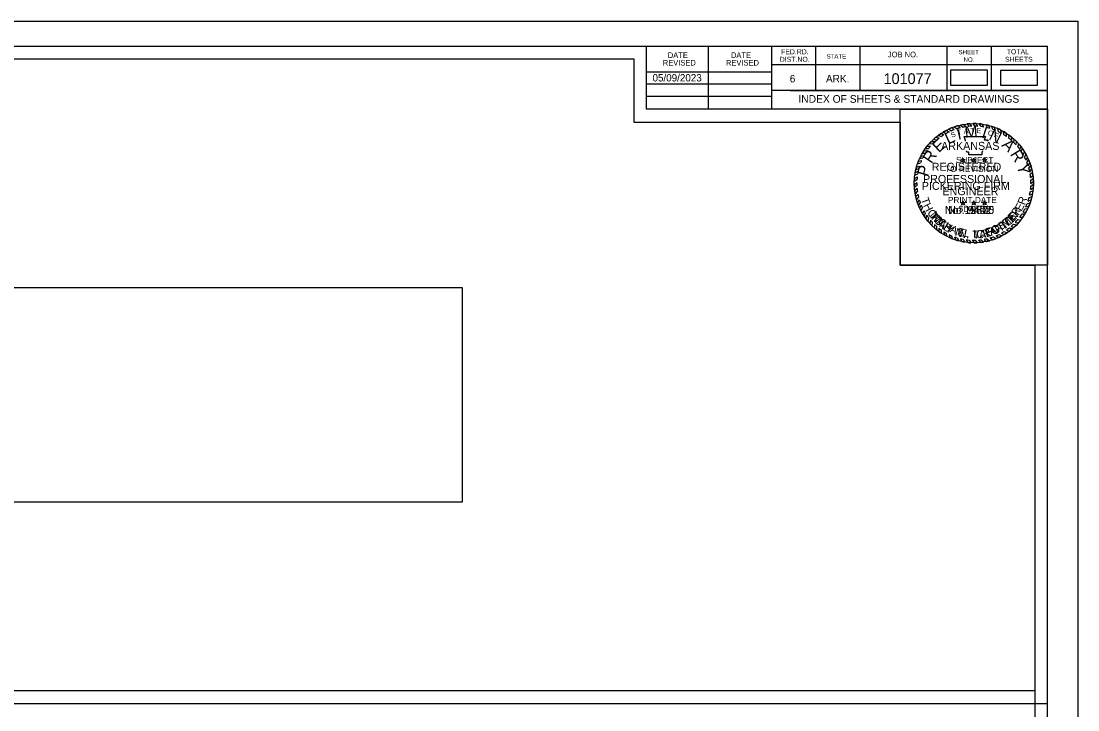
# Model space of a CAD drawing. Extents: x 1369905 to 1370238, y 380119 to 380332.
# Drawn here: x 1370072.9 to 1370238, y 380224.8 to 380332.4 of the extents above; entities that cross this region are included whole.
import ezdxf

# ---------------------------------------------------------------- set-up
doc = ezdxf.new("R2010")
doc.units = 0
for name, color, linetype in [('Default', 7, 'Continuous'), ('R_Border', 7, 'Continuous'), ('R_Border Notes', 7, 'Continuous'), ('R_Border Plan-Plan', 7, 'Continuous'), ('R_No Plot', 7, 'Continuous'), ('R_Revision Date Text', 7, 'Continuous'), ('STAMP_PE_CRAFTON', 7, 'Continuous'), ('STAMP_PE_FOSTER', 7, 'Continuous'), ('STAMP_PE_SEAL-INFO', 7, 'Continuous'), ('STAMP_PE_TAEGTMEYER', 7, 'Continuous'), ('STAMP_PE_TXT', 7, 'Continuous'), ('STAMP_PRELIMINARY', 7, 'Continuous')]:
    doc.layers.add(name, color=color, linetype=linetype)

msp = doc.modelspace()

# ---------------------------------------------------------------- linework, layer by layer
at = {"layer": 'Default'}
for points in [[(1370218.08, 380322.41), (1370223.88, 380322.41), (1370223.88, 380324.71), (1370218.08, 380324.71)], [(1370225.91, 380322.39), (1370231.71, 380322.39), (1370231.71, 380324.69), (1370225.91, 380324.69)], [(1369997.28, 380257.3), (1370141.89, 380257.3), (1370141.89, 380290.72), (1369997.28, 380290.72)]]:
    msp.add_lwpolyline(points, close=True, dxfattribs=at)
at = {"layer": 'R_Border'}
for p, q in [((1369917.07, 380328.5), (1370233.25, 380328.5)), ((1370170.61, 380318.62), (1370170.61, 380328.5)), ((1370180.29, 380318.62), (1370180.29, 380328.5)), ((1370190.15, 380328.5), (1370190.15, 380318.62)), ((1370196.99, 380328.5), (1370196.99, 380321.56)), ((1370203.93, 380328.5), (1370203.93, 380321.56)), ((1370217.51, 380328.5), (1370217.51, 380321.56)), ((1370224.45, 380328.5), (1370224.45, 380321.56)), ((1370233.25, 380123.04), (1370233.25, 380328.5)), ((1370170.61, 380324.48), (1370190.15, 380324.48)), ((1370233.25, 380325.56), (1370190.15, 380325.56)), ((1370233.25, 380325.58), (1370233.25, 380325.58)), ((1370170.61, 380322.62), (1370190.15, 380322.62)), ((1370233.25, 380321.56), (1370190.15, 380321.56)), ((1370193.11, 380321.56), (1370233.25, 380321.56)), ((1370170.61, 380320.68), (1370190.15, 380320.68)), ((1370233.25, 380318.62), (1370170.61, 380318.62))]:
    msp.add_line(p, q, dxfattribs=at)
at = {"layer": 'R_Border Plan-Plan'}
msp.add_line((1369917.07, 380225.77), (1370233.25, 380225.77), dxfattribs=at)
at = {"layer": 'R_No Plot'}
for points in [[(1369904.66, 380332.4), (1370238, 380332.4), (1370238, 380119.06), (1369904.66, 380119.06)], [(1370231.25, 380227.77), (1369919.07, 380227.77), (1369919.07, 380326.5), (1370168.61, 380326.5), (1370168.61, 380316.62), (1370186.15, 380316.62), (1370210.25, 380316.62), (1370210.25, 380294.29), (1370231.25, 380294.29)], [(1369919.07, 380326.5), (1370168.61, 380326.5), (1370168.61, 380316.62), (1370186.15, 380316.62), (1370210.25, 380316.62), (1370210.25, 380294.29), (1370231.25, 380294.29), (1370231.25, 380125.04), (1369919.07, 380125.04)], [(1370210.25, 380318.62), (1370233.25, 380318.62), (1370233.25, 380294.29), (1370210.25, 380294.29)]]:
    msp.add_lwpolyline(points, close=True, dxfattribs=at)
at = {"layer": 'STAMP_PE_SEAL-INFO'}
for p, q in [((1370218.71, 380315.88), (1370219.09, 380315.57)), ((1370219.3, 380316.06), (1370219.58, 380315.71)), ((1370219.68, 380316.16), (1370220.04, 380315.81)), ((1370220.17, 380316.25), (1370220.47, 380315.89)), ((1370220.68, 380316.33), (1370220.96, 380315.95)), ((1370221.42, 380315.97), (1370221.11, 380316.37)), ((1370221.92, 380315.98), (1370221.64, 380316.39)), ((1370222.37, 380315.96), (1370222.12, 380316.38)), ((1370222.88, 380315.91), (1370222.59, 380316.35)), ((1370223.3, 380315.84), (1370223.05, 380316.3)), ((1370223.87, 380315.72), (1370223.69, 380316.18)), ((1370224.27, 380315.62), (1370224.11, 380316.08)), ((1370224.72, 380315.47), (1370224.58, 380315.95)), ((1370215.79, 380314.24), (1370216.32, 380314.13)), ((1370216.16, 380314.56), (1370216.62, 380314.36)), ((1370216.58, 380314.83), (1370217.03, 380314.63)), ((1370216.97, 380315.07), (1370217.4, 380314.85)), ((1370217.42, 380315.32), (1370217.88, 380315.1)), ((1370217.85, 380315.54), (1370218.24, 380315.26)), ((1370218.36, 380315.75), (1370218.65, 380315.43)), ((1370220.22, 380314.36), (1370223.56, 380314.36)), ((1370220.34, 380314.05), (1370220.22, 380314.36)), ((1370223.56, 380314.36), (1370223.34, 380313.87)), ((1370225.14, 380315.31), (1370224.99, 380315.8)), ((1370225.6, 380315.1), (1370225.5, 380315.6)), ((1370226.05, 380314.87), (1370225.96, 380315.38)), ((1370226.43, 380314.65), (1370226.39, 380315.15)), ((1370226.87, 380314.36), (1370226.84, 380314.88)), ((1370227.23, 380314.09), (1370227.26, 380314.58)), ((1370227.68, 380313.72), (1370227.69, 380314.24)), ((1370214.44, 380312.86), (1370214.99, 380312.88)), ((1370214.78, 380313.27), (1370215.31, 380313.23)), ((1370215.11, 380313.61), (1370215.65, 380313.57)), ((1370215.44, 380313.94), (1370215.9, 380313.8)), ((1370220.44, 380313.75), (1370220.34, 380314.05)), ((1370220.45, 380313.64), (1370220.44, 380313.75)), ((1370223.34, 380313.87), (1370223.97, 380313.87)), ((1370223.97, 380313.87), (1370223.83, 380313.64)), ((1370227.99, 380313.43), (1370228.06, 380313.93)), ((1370228.35, 380313.06), (1370228.41, 380313.58)), ((1370228.62, 380312.74), (1370228.76, 380313.21)), ((1370228.94, 380312.32), (1370229.08, 380312.82)), ((1370213.26, 380310.93), (1370213.76, 380311.03)), ((1370213.45, 380311.32), (1370213.95, 380311.38)), ((1370213.68, 380311.74), (1370214.17, 380311.76)), ((1370213.93, 380312.14), (1370214.44, 380312.18)), ((1370214.16, 380312.49), (1370214.67, 380312.48)), ((1370220.64, 380311.93), (1370220.62, 380312.15)), ((1370220.96, 380311.93), (1370220.64, 380311.93)), ((1370220.96, 380311.5), (1370220.96, 380311.93)), ((1370222.99, 380311.5), (1370220.96, 380311.5)), ((1370223, 380311.84), (1370222.99, 380311.5)), ((1370223.08, 380312.15), (1370223, 380311.84)), ((1370229.16, 380312.01), (1370229.34, 380312.47)), ((1370229.47, 380311.51), (1370229.66, 380312)), ((1370229.67, 380311.14), (1370229.9, 380311.59)), ((1370229.9, 380310.66), (1370230.13, 380311.14)), ((1370212.67, 380309.18), (1370213.14, 380309.37)), ((1370212.77, 380309.59), (1370213.25, 380309.76)), ((1370212.93, 380310.09), (1370213.41, 380310.23)), ((1370213.08, 380310.5), (1370213.58, 380310.64)), ((1370230.04, 380310.32), (1370230.31, 380310.76)), ((1370230.24, 380309.77), (1370230.51, 380310.25)), ((1370230.35, 380309.41), (1370230.64, 380309.86)), ((1370230.48, 380308.85), (1370230.8, 380309.3)), ((1370212.85, 380307.61), (1370212.43, 380307.36)), ((1370212.89, 380308.04), (1370212.45, 380307.76)), ((1370212.94, 380308.48), (1370212.5, 380308.25)), ((1370213.03, 380308.93), (1370212.56, 380308.69)), ((1370230.55, 380308.47), (1370230.9, 380308.82)), ((1370230.61, 380307.96), (1370230.99, 380308.3)), ((1370230.65, 380307.54), (1370231.04, 380307.83)), ((1370212.83, 380307.12), (1370212.43, 380306.79)), ((1370212.84, 380306.71), (1370212.45, 380306.39)), ((1370212.87, 380306.22), (1370212.5, 380305.86)), ((1370230.61, 380306.11), (1370231.04, 380306.37)), ((1370230.65, 380306.62), (1370231.07, 380306.9)), ((1370230.66, 380307.02), (1370231.06, 380307.35)), ((1370212.92, 380305.79), (1370212.57, 380305.42)), ((1370213, 380305.33), (1370212.66, 380304.96)), ((1370213.1, 380304.91), (1370212.78, 380304.5)), ((1370213.22, 380304.46), (1370212.93, 380304.05)), ((1370230.21, 380304.28), (1370230.7, 380304.48)), ((1370230.36, 380304.77), (1370230.83, 380304.97)), ((1370230.47, 380305.22), (1370230.92, 380305.42)), ((1370230.56, 380305.72), (1370231, 380305.94)), ((1370213.36, 380304.04), (1370213.08, 380303.63)), ((1370213.53, 380303.62), (1370213.27, 380303.19)), ((1370213.7, 380303.23), (1370213.47, 380302.77)), ((1370213.93, 380302.77), (1370213.74, 380302.28)), ((1370229.7, 380303.05), (1370230.19, 380303.12)), ((1370229.86, 380303.38), (1370230.35, 380303.48)), ((1370230.08, 380303.9), (1370230.56, 380304.03)), ((1370214.17, 380302.37), (1370213.99, 380301.9)), ((1370214.37, 380302.06), (1370214.26, 380301.51)), ((1370214.65, 380301.67), (1370214.55, 380301.14)), ((1370214.96, 380301.29), (1370214.87, 380300.77)), ((1370228.61, 380301.38), (1370229.07, 380301.3)), ((1370228.92, 380301.77), (1370229.42, 380301.78)), ((1370229.26, 380302.27), (1370229.74, 380302.26)), ((1370229.43, 380302.55), (1370229.93, 380302.6)), ((1370215.26, 380300.95), (1370215.2, 380300.43)), ((1370215.58, 380300.63), (1370215.55, 380300.1)), ((1370215.93, 380300.31), (1370215.92, 380299.79)), ((1370216.29, 380300.02), (1370216.3, 380299.5)), ((1370216.62, 380299.77), (1370216.66, 380299.25)), ((1370217.05, 380299.49), (1370217.11, 380298.98)), ((1370226.49, 380299.52), (1370226.94, 380299.33)), ((1370226.84, 380299.75), (1370227.27, 380299.56)), ((1370227.3, 380300.09), (1370227.76, 380299.95)), ((1370227.57, 380300.32), (1370228.04, 380300.19)), ((1370227.97, 380300.69), (1370228.41, 380300.55)), ((1370228.23, 380300.95), (1370228.7, 380300.86)), ((1370217.4, 380299.28), (1370217.49, 380298.77)), ((1370217.88, 380299.03), (1370218.04, 380298.51)), ((1370218.26, 380298.86), (1370218.43, 380298.35)), ((1370218.75, 380298.67), (1370218.96, 380298.17)), ((1370219.16, 380298.54), (1370219.38, 380298.05)), ((1370219.67, 380298.4), (1370219.88, 380297.93)), ((1370220.06, 380298.31), (1370220.31, 380297.85)), ((1370220.56, 380298.23), (1370220.8, 380297.79)), ((1370221, 380298.18), (1370221.27, 380297.76)), ((1370221.48, 380298.16), (1370221.79, 380297.74)), ((1370221.94, 380298.15), (1370222.29, 380297.76)), ((1370222.46, 380298.18), (1370222.79, 380297.8)), ((1370222.9, 380298.23), (1370223.27, 380297.87)), ((1370223.35, 380298.3), (1370223.73, 380297.96)), ((1370223.84, 380298.4), (1370224.22, 380298.08)), ((1370224.3, 380298.53), (1370224.71, 380298.23)), ((1370224.79, 380298.69), (1370225.23, 380298.42)), ((1370225.21, 380298.85), (1370225.63, 380298.59)), ((1370225.67, 380299.06), (1370226.15, 380298.85)), ((1370226.08, 380299.28), (1370226.49, 380299.04))]:
    msp.add_line(p, q, dxfattribs=at)
for radius, start, end in [(9.32, 105.2339, 109.0352), (9.32, 99.7525, 102.7765), (8.91, 98.258, 101.0329), (9.32, 93.9381, 96.5517), (8.91, 92.1102, 95.0367), (9.32, 87.7298, 90.6707), (8.91, 85.9628, 88.9097), (9.32, 81.9732, 84.8236), (8.91, 79.9264, 82.696), (9.32, 75.3125, 77.9426), (9.32, 69.6061, 72.3058), (9.32, 129.7326, 132.5376), (9.32, 123.6199, 126.5906), (8.91, 121.9746, 125.11), (9.32, 117.6544, 120.8099), (8.91, 115.6869, 119.1583), (9.32, 111.3124, 114.7026), (8.91, 110.3086, 113.1659), (8.91, 104.0352, 107.3615), (8.91, 73.5575, 76.2314), (8.91, 67.6248, 70.504), (9.32, 63.1329, 66.2704), (8.91, 61.1558, 64.3784), (9.32, 56.9003, 60.0942), (8.91, 54.9238, 58.2702), (9.32, 50.3492, 53.7159), (9.32, 141.6056, 144.4486), (8.91, 139.301, 142.5873), (9.32, 135.4021, 138.3031), (8.91, 133.1331, 136.2562), (8.91, 127.5297, 130.9683), (8.91, 48.3016, 52.0395), (8.91, 42.2212, 45.5512), (9.32, 44.3405, 47.3929), (8.91, 36.135, 39.5311), (9.32, 38.1247, 41.2316), (9.32, 152.864, 155.5189), (9.32, 147.0072, 149.899), (8.91, 151.0315, 153.573), (8.91, 145.0197, 148.2104), (8.91, 29.9032, 33.6645), (9.32, 31.9614, 35.4294), (8.91, 23.7732, 27.2211), (9.32, 25.9391, 29.0125), (9.32, 164.3068, 166.894), (9.32, 158.4077, 161.0701), (8.91, 162.4331, 165.0013), (8.91, 156.3402, 159.2319), (8.91, 17.6802, 21.4251), (9.32, 19.9538, 23.3141), (8.91, 11.5444, 15.2364), (9.32, 13.8421, 17.4447), (9.32, 175.7409, 178.2066), (9.32, 170.0003, 172.6878), (8.91, 173.73, 176.4734), (8.91, 167.9048, 170.9039), (8.91, 5.7599, 9.0606), (9.32, 7.5852, 10.8621), (9.32, 1.7215, 4.7268), (9.32, 181.7251, 184.1626), (8.91, 179.6454, 182.2633), (8.91, 185.4539, 188.234), (8.91, 353.8632, 357.1274), (8.91, 359.7329, 3.0639), (9.32, 355.7156, 358.9569), (9.32, 187.4204, 190.1927), (9.32, 193.0369, 195.9973), (8.91, 191.2274, 193.9858), (8.91, 196.9675, 199.8353), (8.91, 341.777, 345.0925), (8.91, 348.0778, 351.3435), (9.32, 343.8925, 347.035), (9.32, 349.8305, 353.0885), (9.32, 198.8967, 201.6281), (9.32, 204.5479, 207.4328), (8.91, 202.7761, 205.4791), (8.91, 208.7883, 211.7934), (8.91, 329.5549, 333.2076), (8.91, 335.6038, 339.1858), (9.32, 331.4037, 334.9332), (9.32, 337.3837, 340.9933), (9.32, 210.8636, 213.6571), (9.32, 216.6115, 219.491), (8.91, 214.1838, 217.2747), (8.91, 220.3909, 223.3056), (8.91, 316.6531, 320.3711), (9.32, 318.2846, 321.8043), (8.91, 323.5851, 327.4407), (9.32, 325.4405, 328.9872), (9.32, 222.48, 225.3801), (9.32, 228.3665, 231.348), (8.91, 226.2494, 229.2407), (8.91, 232.229, 234.9336), (9.32, 234.295, 236.9452), (8.91, 238.2223, 240.8353), (8.91, 299.0768, 302.1724), (8.91, 304.823, 308.5143), (9.32, 306.3721, 310.208), (8.91, 310.7744, 314.3161), (9.32, 312.4518, 315.6633), (9.32, 240.1977, 242.8613), (8.91, 244.3204, 246.9486), (9.32, 246.576, 249.1558), (8.91, 250.3491, 253.1216), (9.32, 252.5967, 255.3252), (8.91, 256.505, 259.1192), (9.32, 258.4433, 261.1398), (8.91, 262.3783, 265.2012), (9.32, 264.1978, 267.1009), (8.91, 268.3215, 271.277), (9.32, 270.2548, 273.3361), (8.91, 274.6157, 277.4486), (9.32, 276.4239, 279.4357), (8.91, 280.3459, 283.5814), (9.32, 282.3199, 285.3702), (8.91, 286.6423, 289.9783), (9.32, 288.5709, 291.9733), (8.91, 292.8745, 296.1185), (9.32, 294.6481, 298.2166), (9.32, 300.621, 303.8703)]:
    msp.add_arc((1370221.75, 380307.07), radius, start, end, dxfattribs=at)
at = {"layer": 'STAMP_PE_TXT'}
for p, q in [((1370219.97, 380310.78), (1370220.05, 380311.01)), ((1370220.05, 380311.01), (1370220.12, 380310.78)), ((1370221.67, 380310.78), (1370221.75, 380311.01)), ((1370221.75, 380311.01), (1370221.82, 380310.78)), ((1370223.37, 380310.78), (1370223.44, 380311.01)), ((1370223.44, 380311.01), (1370223.52, 380310.78)), ((1370219.93, 380310.64), (1370219.73, 380310.78)), ((1370219.73, 380310.78), (1370219.97, 380310.78)), ((1370219.85, 380310.4), (1370219.93, 380310.64)), ((1370220.05, 380310.55), (1370219.85, 380310.4)), ((1370220.25, 380310.4), (1370220.05, 380310.55)), ((1370220.12, 380310.78), (1370220.37, 380310.78)), ((1370220.37, 380310.78), (1370220.17, 380310.64)), ((1370220.17, 380310.64), (1370220.25, 380310.4)), ((1370221.62, 380310.64), (1370221.42, 380310.78)), ((1370221.42, 380310.78), (1370221.67, 380310.78)), ((1370221.55, 380310.4), (1370221.62, 380310.64)), ((1370221.75, 380310.55), (1370221.55, 380310.4)), ((1370221.94, 380310.4), (1370221.75, 380310.55)), ((1370221.82, 380310.78), (1370222.07, 380310.78)), ((1370222.07, 380310.78), (1370221.87, 380310.64)), ((1370221.87, 380310.64), (1370221.94, 380310.4)), ((1370223.32, 380310.64), (1370223.12, 380310.78)), ((1370223.12, 380310.78), (1370223.37, 380310.78)), ((1370223.25, 380310.4), (1370223.32, 380310.64)), ((1370223.44, 380310.55), (1370223.25, 380310.4)), ((1370223.64, 380310.4), (1370223.44, 380310.55)), ((1370223.52, 380310.78), (1370223.76, 380310.78)), ((1370223.76, 380310.78), (1370223.57, 380310.64)), ((1370223.57, 380310.64), (1370223.64, 380310.4)), ((1370219.93, 380303.93), (1370219.73, 380304.07)), ((1370219.73, 380304.07), (1370219.97, 380304.07)), ((1370219.85, 380303.7), (1370219.93, 380303.93)), ((1370220.05, 380303.84), (1370219.85, 380303.7)), ((1370219.97, 380304.07), (1370220.05, 380304.31)), ((1370220.05, 380304.31), (1370220.12, 380304.07)), ((1370220.25, 380303.7), (1370220.05, 380303.84)), ((1370220.12, 380304.07), (1370220.37, 380304.07)), ((1370220.37, 380304.07), (1370220.17, 380303.93)), ((1370220.17, 380303.93), (1370220.25, 380303.7)), ((1370221.62, 380303.93), (1370221.42, 380304.07)), ((1370221.42, 380304.07), (1370221.67, 380304.07)), ((1370221.55, 380303.7), (1370221.62, 380303.93)), ((1370221.75, 380303.84), (1370221.55, 380303.7)), ((1370221.67, 380304.07), (1370221.75, 380304.31)), ((1370221.75, 380304.31), (1370221.82, 380304.07)), ((1370221.94, 380303.7), (1370221.75, 380303.84)), ((1370221.82, 380304.07), (1370222.07, 380304.07)), ((1370222.07, 380304.07), (1370221.87, 380303.93)), ((1370221.87, 380303.93), (1370221.94, 380303.7)), ((1370223.32, 380303.93), (1370223.12, 380304.07)), ((1370223.12, 380304.07), (1370223.37, 380304.07)), ((1370223.25, 380303.7), (1370223.32, 380303.93)), ((1370223.44, 380303.84), (1370223.25, 380303.7)), ((1370223.37, 380304.07), (1370223.44, 380304.31)), ((1370223.44, 380304.31), (1370223.52, 380304.07)), ((1370223.64, 380303.7), (1370223.44, 380303.84)), ((1370223.52, 380304.07), (1370223.76, 380304.07)), ((1370223.76, 380304.07), (1370223.57, 380303.93)), ((1370223.57, 380303.93), (1370223.64, 380303.7))]:
    msp.add_line(p, q, dxfattribs=at)
at = {"layer": 'STAMP_PRELIMINARY'}
msp.add_circle((1370221.75, 380307.07), 9.32, dxfattribs=at)

# ---------------------------------------------------------------- texts
at = {"layer": 'R_Border'}
for s, height, p in [('DATE', 0.879, (1370173.94, 380326.64)), ('DATE', 0.879, (1370183.8, 380326.64)), ('FED.RD.', 0.782, (1370191.63, 380327.22)), ('JOB NO.', 0.879, (1370208.33, 380326.74)), ('SHEET', 0.684, (1370219.37, 380327.22)), ('TOTAL', 0.782, (1370226.89, 380327.22)), ('REVISED', 0.879, (1370173.16, 380325.46)), ('REVISED', 0.879, (1370183.02, 380325.46)), ('DIST.NO.', 0.782, (1370191.43, 380326.04)), ('STATE', 0.684, (1370198.75, 380326.54)), ('NO.', 0.684, (1370220.15, 380326.04)), ('SHEETS', 0.782, (1370226.61, 380326.04)), ('6', 1.17, (1370192.99, 380322.82)), ('ARK.', 1.172, (1370198.65, 380322.82))]:
    msp.add_text(s, height=height, dxfattribs=at).set_placement(p)
at = {"layer": 'R_Border Notes'}
for s, height, p in [('101077', 1.68, (1370207.65, 380322.57)), ('INDEX OF SHEETS & STANDARD DRAWINGS', 1.2, (1370194.34, 380319.64))]:
    msp.add_text(s, height=height, dxfattribs=at).set_placement(p)
at = {"layer": 'R_Revision Date Text'}
msp.add_text('05/09/2023', height=1.15, dxfattribs=at).set_placement((1370171.55, 380322.97))
at = {"layer": 'STAMP_PE_CRAFTON'}
for s, rotation, p in [('T', 310.7442, (1370214.71, 380301.96)), ('N', 49.2411, (1370228.03, 380301.09)), ('O', 317.6422, (1370215.38, 380301.15)), ('N', 324.4537, (1370216.22, 380300.37)), ('T', 34.1136, (1370226.32, 380299.71)), ('O', 41.8391, (1370227.18, 380300.31)), ('Y', 331.1686, (1370217.26, 380299.65)), ('N', 347.4752, (1370219.31, 380298.74)), ('C', 6.0117, (1370222.22, 380298.41)), ('R', 14.8189, (1370223.31, 380298.52)), ('A', 20.5125, (1370224.43, 380298.82)), ('F', 28.7821, (1370225.41, 380299.2)), ('.', 356.8926, (1370220.54, 380298.46))]:
    msp.add_text(s, height=1.25, rotation=rotation, dxfattribs=at).set_placement(p)
msp.add_text('No. 12370', height=1.25, dxfattribs=at).set_placement((1370217.21, 380302.26))
at = {"layer": 'STAMP_PE_FOSTER'}
for s, rotation, p in [('M', 308.339, (1370214.86, 380302.09)), ('R', 54.5031, (1370228.47, 380301.88)), ('I', 314.1842, (1370215.66, 380301.15)), ('C', 319.8733, (1370216.01, 380300.8)), ('S', 31.7234, (1370225.94, 380299.68)), ('T', 39.4194, (1370226.89, 380300.31)), ('E', 46.9613, (1370227.75, 380301.06)), ('H', 327.7235, (1370216.94, 380300.06)), ('A', 335.7276, (1370217.92, 380299.48)), ('E', 343.5779, (1370219.06, 380299.01)), ('L', 350.8115, (1370220.12, 380298.73)), ('L', 1.2666, (1370221.66, 380298.57)), ('F', 15.8691, (1370223.78, 380298.82)), ('O', 23.719, (1370224.83, 380299.15)), ('.', 6.8035, (1370222.71, 380298.63))]:
    msp.add_text(s, height=1.2, rotation=rotation, dxfattribs=at).set_placement(p)
msp.add_text('No. 9402', height=1.25, dxfattribs=at).set_placement((1370217.73, 380302.26))
at = {"layer": 'STAMP_PE_TAEGTMEYER'}
for s, rotation, p in [('T', 289.646, (1370213.44, 380304.58)), ('R', 69.57, (1370229.69, 380303.58)), ('H', 296.7339, (1370213.8, 380303.59)), ('O', 303.7708, (1370214.39, 380302.48)), ('Y', 53.9986, (1370228.52, 380301.66)), ('E', 63.0984, (1370229.19, 380302.6)), ('M', 314.2033, (1370215.05, 380301.53)), ('A', 321.0594, (1370216.01, 380300.57)), ('M', 39.3, (1370226.74, 380299.96)), ('E', 46.8094, (1370227.78, 380300.84)), ('S', 327.8239, (1370216.84, 380299.92)), ('N', 344.2727, (1370218.73, 380298.92)), ('T', 3.0061, (1370221.61, 380298.39)), ('A', 8.9826, (1370222.66, 380298.44)), ('E', 17.6836, (1370223.7, 380298.6)), ('G', 23.3052, (1370224.75, 380298.93)), ('T', 31.466, (1370225.85, 380299.42)), ('.', 350.6464, (1370219.95, 380298.59))]:
    msp.add_text(s, height=1.25, rotation=rotation, dxfattribs=at).set_placement(p)
msp.add_text('No. 19605', height=1.25, dxfattribs=at).set_placement((1370217.21, 380302.26))
at = {"layer": 'STAMP_PE_TXT'}
for s, rotation, p in [('S', 23.5541, (1370218.34, 380314.17)), ('T', 16.311, (1370219.27, 380314.54)), ('A', 9.0679, (1370220.23, 380314.79)), ('T', 1.8248, (1370221.22, 380314.92)), ('E', 355.2002, (1370222.13, 380314.93)), ('O', 342.2506, (1370223.85, 380314.66)), ('F', 335.0075, (1370224.82, 380314.32))]:
    msp.add_text(s, height=0.781, rotation=rotation, dxfattribs=at).set_placement(p)
for s, p in [('ARKANSAS', (1370216.64, 380312.28)), ('REGISTERED', (1370215.16, 380309.01)), ('PROFESSIONAL', (1370213.81, 380307.11)), ('ENGINEER', (1370216.85, 380305.2))]:
    msp.add_text(s, height=1.25, dxfattribs=at).set_placement(p)
at = {"layer": 'STAMP_PRELIMINARY'}
for s, rotation, p in [('M', 3.1074, (1370220.38, 380314.16)), ('I', 342.3164, (1370222.85, 380314.23)), ('L', 25.513, (1370217.75, 380313.09)), ('I', 12.5248, (1370219.28, 380313.85)), ('N', 333.9382, (1370223.96, 380313.96)), ('E', 42.3578, (1370216.27, 380311.76)), ('A', 315.6579, (1370225.99, 380312.93)), ('R', 56.2292, (1370215.12, 380310.03)), ('R', 301.3831, (1370227.36, 380311.62)), ('P', 73.913, (1370214.57, 380308.01)), ('Y', 283.2593, (1370228.45, 380309.83))]:
    msp.add_text(s, height=1.8, rotation=rotation, dxfattribs=at).set_placement(p)
for s, height, p in [('SUBJECT', 0.96, (1370218.95, 380310.22)), ('TO REVISION', 0.96, (1370217.28, 380308.83)), ('PICKERING FIRM', 1.25, (1370213.62, 380306.03)), ('PRINT DATE', 0.96, (1370217.7, 380303.98)), ('$DATE$', 0.96, (1370219.38, 380302.6))]:
    msp.add_text(s, height=height, dxfattribs=at).set_placement(p)

doc.saveas('drawing.dxf')
